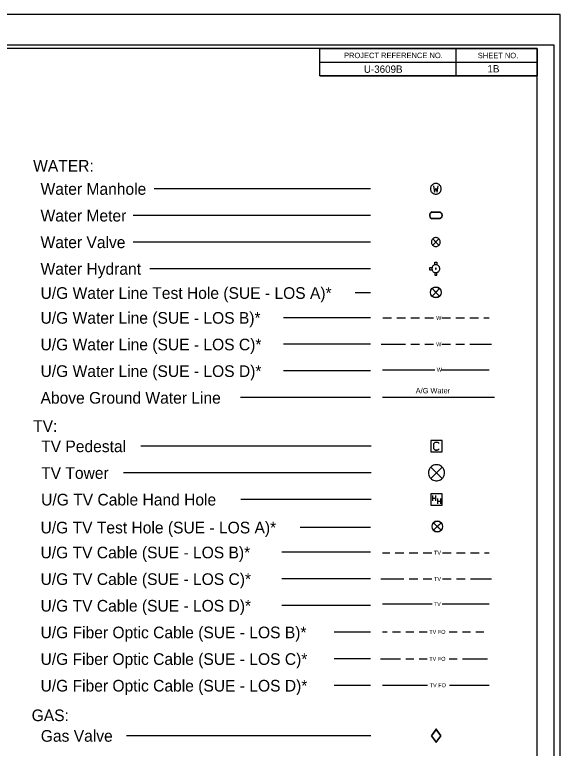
# Model space of a CAD drawing. Extents: x 2594871.4 to 2594905.1, y 784137.6 to 784159.6.
# Drawn here: x 2594897.02 to 2594905.05, y 784148.76 to 784159.56 of the extents above; entities that cross this region are included whole.
import ezdxf

# ---------------------------------------------------------------- set-up
doc = ezdxf.new("R2010")
doc.units = 0
for name, color, linetype in [('Default', 7, 'Continuous'), ('Sheet Data Field CELL', 7, 'Continuous'), ('Sheet Plot Border Inside CELL', 7, 'Continuous'), ('Sheet Plot Border Outside CELL', 7, 'Continuous'), ('Sheet Symbology CELL', 7, 'Continuous')]:
    doc.layers.add(name, color=color, linetype=linetype)

msp = doc.modelspace()

# ---------------------------------------------------------------- linework, layer by layer
at = {"layer": 'Default'}
for p, q in [((2594902.258, 784156.999), (2594899.072, 784156.999)), ((2594902.258, 784156.606), (2594898.765, 784156.606)), ((2594903.159, 784156.657), (2594903.28, 784156.657)), ((2594903.159, 784156.653), (2594903.28, 784156.653)), ((2594903.279, 784156.561), (2594903.159, 784156.561)), ((2594903.279, 784156.557), (2594903.159, 784156.557)), ((2594902.258, 784156.214), (2594898.765, 784156.214)), ((2594902.258, 784155.822), (2594899.006, 784155.822)), ((2594902.258, 784155.467), (2594902.031, 784155.467)), ((2594902.258, 784155.101), (2594900.975, 784155.101)), ((2594902.438, 784155.097), (2594902.565, 784155.097)), ((2594902.644, 784155.097), (2594902.771, 784155.097)), ((2594902.85, 784155.097), (2594902.977, 784155.097)), ((2594903.056, 784155.097), (2594903.183, 784155.097)), ((2594903.309, 784155.097), (2594903.436, 784155.097)), ((2594903.515, 784155.097), (2594903.642, 784155.097)), ((2594903.72, 784155.097), (2594903.848, 784155.097)), ((2594903.926, 784155.097), (2594904.004, 784155.097)), ((2594902.258, 784154.709), (2594900.975, 784154.709)), ((2594902.415, 784154.709), (2594902.771, 784154.709)), ((2594902.85, 784154.709), (2594902.977, 784154.709)), ((2594903.056, 784154.709), (2594903.183, 784154.709)), ((2594903.309, 784154.709), (2594903.436, 784154.709)), ((2594903.515, 784154.709), (2594903.642, 784154.709)), ((2594903.72, 784154.709), (2594904.04, 784154.709)), ((2594902.258, 784154.317), (2594900.975, 784154.317)), ((2594902.434, 784154.334), (2594903.205, 784154.334)), ((2594903.303, 784154.334), (2594904.004, 784154.334)), ((2594902.258, 784153.924), (2594900.341, 784153.924)), ((2594902.434, 784153.929), (2594904.082, 784153.929)), ((2594902.267, 784153.21), (2594898.875, 784153.21)), ((2594903.216, 784153.152), (2594903.241, 784153.152)), ((2594902.267, 784152.817), (2594898.622, 784152.817)), ((2594903.168, 784152.484), (2594903.168, 784152.405)), ((2594903.213, 784152.484), (2594903.213, 784152.405)), ((2594902.267, 784152.425), (2594900.35, 784152.425)), ((2594903.168, 784152.444), (2594903.213, 784152.444)), ((2594903.244, 784152.441), (2594903.244, 784152.362)), ((2594903.244, 784152.401), (2594903.289, 784152.401)), ((2594903.289, 784152.441), (2594903.289, 784152.362)), ((2594902.258, 784152.014), (2594901.221, 784152.014)), ((2594902.258, 784151.647), (2594900.95, 784151.647)), ((2594902.434, 784151.641), (2594902.544, 784151.641)), ((2594902.622, 784151.641), (2594902.75, 784151.641)), ((2594902.828, 784151.641), (2594902.956, 784151.641)), ((2594903.034, 784151.641), (2594903.162, 784151.641)), ((2594903.319, 784151.641), (2594903.446, 784151.641)), ((2594903.525, 784151.641), (2594903.652, 784151.641)), ((2594903.731, 784151.641), (2594903.858, 784151.641)), ((2594903.937, 784151.641), (2594904.004, 784151.641)), ((2594902.258, 784151.255), (2594900.95, 784151.255)), ((2594902.407, 784151.255), (2594902.75, 784151.255)), ((2594902.828, 784151.255), (2594902.956, 784151.255)), ((2594903.034, 784151.255), (2594903.162, 784151.255)), ((2594903.319, 784151.255), (2594903.446, 784151.255)), ((2594903.525, 784151.255), (2594903.652, 784151.255)), ((2594903.731, 784151.255), (2594904.037, 784151.255)), ((2594902.258, 784150.863), (2594900.95, 784150.863)), ((2594902.434, 784150.886), (2594903.164, 784150.886)), ((2594903.311, 784150.886), (2594904.004, 784150.886)), ((2594902.258, 784150.47), (2594901.723, 784150.47)), ((2594902.434, 784150.475), (2594902.503, 784150.475)), ((2594902.582, 784150.475), (2594902.699, 784150.475)), ((2594902.778, 784150.475), (2594902.895, 784150.475)), ((2594902.974, 784150.475), (2594903.092, 784150.475)), ((2594903.415, 784150.475), (2594903.533, 784150.475)), ((2594903.611, 784150.475), (2594903.729, 784150.475)), ((2594903.808, 784150.475), (2594903.925, 784150.475)), ((2594902.258, 784150.078), (2594901.723, 784150.078)), ((2594902.402, 784150.078), (2594902.699, 784150.078)), ((2594902.778, 784150.078), (2594902.895, 784150.078)), ((2594902.974, 784150.078), (2594903.092, 784150.078)), ((2594903.415, 784150.078), (2594903.533, 784150.078)), ((2594903.611, 784150.078), (2594903.979, 784150.078)), ((2594902.258, 784149.686), (2594901.723, 784149.686)), ((2594902.434, 784149.69), (2594903.097, 784149.69)), ((2594903.421, 784149.69), (2594904.004, 784149.69)), ((2594903.223, 784149.039), (2594903.154, 784148.947)), ((2594903.292, 784148.947), (2594903.223, 784149.039)), ((2594902.262, 784148.947), (2594898.663, 784148.947)), ((2594903.154, 784148.947), (2594903.223, 784148.854)), ((2594903.223, 784148.854), (2594903.292, 784148.947))]:
    msp.add_line(p, q, dxfattribs=at)
for points in [[(2594903.219, 784157.078), (2594903.209, 784157.078), (2594903.199, 784157.076), (2594903.19, 784157.073), (2594903.181, 784157.068), (2594903.173, 784157.063), (2594903.165, 784157.057), (2594903.158, 784157.049), (2594903.152, 784157.041), (2594903.147, 784157.033), (2594903.144, 784157.023), (2594903.141, 784157.013), (2594903.14, 784157.004), (2594903.14, 784156.994), (2594903.141, 784156.984), (2594903.144, 784156.974), (2594903.147, 784156.965), (2594903.152, 784156.956), (2594903.158, 784156.948), (2594903.165, 784156.941), (2594903.173, 784156.934), (2594903.181, 784156.929), (2594903.19, 784156.925), (2594903.199, 784156.922), (2594903.21, 784156.92), (2594903.219, 784156.919), (2594903.229, 784156.92), (2594903.239, 784156.922), (2594903.248, 784156.925), (2594903.257, 784156.929), (2594903.266, 784156.934), (2594903.273, 784156.941), (2594903.28, 784156.948), (2594903.286, 784156.956), (2594903.291, 784156.965), (2594903.294, 784156.975), (2594903.297, 784156.984), (2594903.298, 784156.994), (2594903.298, 784157.004), (2594903.297, 784157.013), (2594903.294, 784157.024), (2594903.291, 784157.033), (2594903.286, 784157.041), (2594903.28, 784157.049), (2594903.273, 784157.057), (2594903.266, 784157.063), (2594903.257, 784157.068), (2594903.248, 784157.073), (2594903.239, 784157.076), (2594903.229, 784157.078), (2594903.219, 784157.078)], [(2594903.183, 784157.043), (2594903.2, 784156.95), (2594903.219, 784157.008), (2594903.239, 784156.95), (2594903.255, 784157.043)], [(2594903.159, 784156.657), (2594903.151, 784156.653), (2594903.144, 784156.647), (2594903.138, 784156.64), (2594903.133, 784156.633), (2594903.129, 784156.625), (2594903.127, 784156.616), (2594903.126, 784156.607), (2594903.127, 784156.598), (2594903.129, 784156.589), (2594903.133, 784156.581), (2594903.138, 784156.573), (2594903.144, 784156.567), (2594903.151, 784156.562), (2594903.159, 784156.557)], [(2594903.161, 784156.654), (2594903.153, 784156.649), (2594903.146, 784156.644), (2594903.14, 784156.636), (2594903.135, 784156.629), (2594903.132, 784156.621), (2594903.13, 784156.611), (2594903.13, 784156.603), (2594903.132, 784156.594), (2594903.135, 784156.585), (2594903.14, 784156.577), (2594903.146, 784156.57), (2594903.153, 784156.565), (2594903.161, 784156.561)], [(2594903.277, 784156.654), (2594903.286, 784156.65), (2594903.293, 784156.644), (2594903.299, 784156.637), (2594903.303, 784156.629), (2594903.307, 784156.621), (2594903.308, 784156.611), (2594903.308, 784156.603), (2594903.307, 784156.593), (2594903.303, 784156.585), (2594903.299, 784156.577), (2594903.292, 784156.57), (2594903.285, 784156.565), (2594903.277, 784156.56)], [(2594903.279, 784156.657), (2594903.287, 784156.653), (2594903.294, 784156.647), (2594903.3, 784156.64), (2594903.305, 784156.633), (2594903.309, 784156.625), (2594903.311, 784156.616), (2594903.312, 784156.607), (2594903.311, 784156.598), (2594903.309, 784156.589), (2594903.305, 784156.581), (2594903.3, 784156.573), (2594903.294, 784156.567), (2594903.287, 784156.562), (2594903.279, 784156.557)], [(2594903.284, 784156.214), (2594903.283, 784156.224), (2594903.281, 784156.234), (2594903.278, 784156.242), (2594903.273, 784156.251), (2594903.267, 784156.258), (2594903.26, 784156.265), (2594903.252, 784156.271), (2594903.243, 784156.275), (2594903.234, 784156.278), (2594903.224, 784156.279), (2594903.214, 784156.279), (2594903.205, 784156.278), (2594903.195, 784156.275), (2594903.186, 784156.271), (2594903.179, 784156.265), (2594903.171, 784156.258), (2594903.166, 784156.251), (2594903.16, 784156.242), (2594903.157, 784156.234), (2594903.155, 784156.224), (2594903.154, 784156.214), (2594903.155, 784156.205), (2594903.157, 784156.195), (2594903.16, 784156.186), (2594903.166, 784156.177), (2594903.171, 784156.17), (2594903.179, 784156.163), (2594903.186, 784156.158), (2594903.195, 784156.153), (2594903.205, 784156.15), (2594903.214, 784156.149), (2594903.224, 784156.149), (2594903.234, 784156.15), (2594903.243, 784156.153), (2594903.252, 784156.158), (2594903.26, 784156.163), (2594903.267, 784156.17), (2594903.273, 784156.177), (2594903.278, 784156.186), (2594903.281, 784156.195), (2594903.283, 784156.205), (2594903.284, 784156.214)], [(2594903.265, 784156.168), (2594903.173, 784156.26), (2594903.219, 784156.214), (2594903.173, 784156.168), (2594903.265, 784156.26)], [(2594903.163, 784155.837), (2594903.126, 784155.837), (2594903.126, 784155.807), (2594903.163, 784155.807)], [(2594903.218, 784155.88), (2594903.209, 784155.879), (2594903.2, 784155.877), (2594903.191, 784155.873), (2594903.184, 784155.868), (2594903.177, 784155.862), (2594903.171, 784155.854), (2594903.166, 784155.846), (2594903.163, 784155.837), (2594903.161, 784155.828), (2594903.161, 784155.819), (2594903.163, 784155.81), (2594903.165, 784155.801), (2594903.169, 784155.793), (2594903.175, 784155.785), (2594903.181, 784155.778), (2594903.189, 784155.772), (2594903.197, 784155.768), (2594903.206, 784155.765), (2594903.215, 784155.764), (2594903.224, 784155.764), (2594903.233, 784155.765), (2594903.242, 784155.769), (2594903.251, 784155.773), (2594903.258, 784155.779), (2594903.264, 784155.786), (2594903.27, 784155.793), (2594903.273, 784155.802), (2594903.276, 784155.811), (2594903.277, 784155.82), (2594903.276, 784155.829), (2594903.275, 784155.838), (2594903.271, 784155.847), (2594903.267, 784155.856), (2594903.26, 784155.863), (2594903.253, 784155.869), (2594903.245, 784155.874), (2594903.236, 784155.877), (2594903.227, 784155.879), (2594903.218, 784155.88)], [(2594903.205, 784155.878), (2594903.205, 784155.916), (2594903.235, 784155.916), (2594903.235, 784155.878)], [(2594903.219, 784155.829), (2594903.216, 784155.828), (2594903.214, 784155.826), (2594903.212, 784155.823), (2594903.213, 784155.82), (2594903.215, 784155.817), (2594903.218, 784155.815), (2594903.221, 784155.815), (2594903.224, 784155.817), (2594903.225, 784155.82), (2594903.226, 784155.823), (2594903.224, 784155.826), (2594903.222, 784155.828), (2594903.219, 784155.829)], [(2594903.205, 784155.765), (2594903.205, 784155.728), (2594903.235, 784155.728), (2594903.235, 784155.766)], [(2594903.274, 784155.529), (2594903.163, 784155.419), (2594903.218, 784155.474), (2594903.163, 784155.529), (2594903.274, 784155.419)], [(2594903.163, 784155.529), (2594903.218, 784155.474), (2594903.274, 784155.529)], [(2594903.274, 784155.419), (2594903.218, 784155.474), (2594903.163, 784155.419)], [(2594903.147, 784153.128), (2594903.31, 784153.128), (2594903.31, 784153.291), (2594903.147, 784153.291), (2594903.147, 784153.128)], [(2594903.267, 784153.17), (2594903.247, 784153.152), (2594903.21, 784153.152), (2594903.191, 784153.17), (2594903.191, 784153.249), (2594903.21, 784153.267), (2594903.247, 784153.267), (2594903.267, 784153.249)], [(2594903.347, 784152.817), (2594903.345, 784152.834), (2594903.341, 784152.853), (2594903.335, 784152.868), (2594903.326, 784152.884), (2594903.315, 784152.897), (2594903.302, 784152.909), (2594903.288, 784152.92), (2594903.272, 784152.928), (2594903.255, 784152.933), (2594903.238, 784152.935), (2594903.219, 784152.935), (2594903.202, 784152.933), (2594903.185, 784152.928), (2594903.169, 784152.92), (2594903.155, 784152.909), (2594903.142, 784152.897), (2594903.131, 784152.884), (2594903.122, 784152.868), (2594903.116, 784152.853), (2594903.112, 784152.834), (2594903.11, 784152.817), (2594903.112, 784152.8), (2594903.116, 784152.782), (2594903.122, 784152.766), (2594903.131, 784152.75), (2594903.142, 784152.737), (2594903.155, 784152.725), (2594903.169, 784152.715), (2594903.185, 784152.707), (2594903.202, 784152.702), (2594903.219, 784152.699), (2594903.238, 784152.699), (2594903.255, 784152.702), (2594903.272, 784152.707), (2594903.288, 784152.715), (2594903.302, 784152.725), (2594903.315, 784152.737), (2594903.326, 784152.75), (2594903.335, 784152.766), (2594903.341, 784152.782), (2594903.345, 784152.8), (2594903.347, 784152.817)], [(2594903.312, 784152.733), (2594903.144, 784152.901), (2594903.228, 784152.817), (2594903.144, 784152.733), (2594903.312, 784152.901)], [(2594903.144, 784152.34), (2594903.313, 784152.34), (2594903.313, 784152.509), (2594903.144, 784152.509), (2594903.144, 784152.34)], [(2594903.296, 784152.082), (2594903.185, 784151.971), (2594903.241, 784152.027), (2594903.185, 784152.082), (2594903.296, 784151.971)], [(2594903.185, 784152.082), (2594903.241, 784152.027), (2594903.296, 784152.082)], [(2594903.296, 784151.971), (2594903.241, 784152.027), (2594903.185, 784151.971)], [(2594903.223, 784149.047), (2594903.148, 784148.947), (2594903.223, 784148.846), (2594903.298, 784148.947), (2594903.223, 784149.047)]]:
    msp.add_lwpolyline(points, dxfattribs=at)
for centre in [(2594903.218, 784155.474), (2594903.241, 784152.027)]:
    msp.add_circle(centre, 0.0784, dxfattribs=at)
for centre, start, end in [((2594903.218, 784155.474), 45, 135), ((2594903.218, 784155.474), 225, 315), ((2594903.241, 784152.027), 45, 135), ((2594903.241, 784152.027), 225, 315)]:
    msp.add_arc(centre, 0.0784, start, end, dxfattribs=at)
at = {"layer": 'Sheet Plot Border Inside CELL'}
msp.add_lwpolyline([(2594871.632, 784138.011), (2594904.962, 784138.011), (2594904.962, 784159.113), (2594871.632, 784159.113)], close=True, dxfattribs=at)
at = {"layer": 'Sheet Plot Border Outside CELL'}
msp.add_lwpolyline([(2594905.052, 784159.562), (2594871.372, 784159.562), (2594871.372, 784137.562), (2594905.052, 784137.562)], close=True, dxfattribs=at)
at = {"layer": 'Sheet Symbology CELL'}
for p, q in [((2594903.512, 784159.061), (2594903.512, 784158.661)), ((2594901.511, 784158.861), (2594904.712, 784158.861)), ((2594901.511, 784158.661), (2594904.712, 784158.661))]:
    msp.add_line(p, q, dxfattribs=at)
for points in [[(2594904.712, 784159.062), (2594874.712, 784159.062), (2594874.712, 784138.082), (2594904.712, 784138.082)], [(2594901.511, 784159.062), (2594904.712, 784159.062), (2594904.712, 784158.661), (2594901.511, 784158.661)]]:
    msp.add_lwpolyline(points, close=True, dxfattribs=at)

# ---------------------------------------------------------------- texts
at = {"layer": 'Default'}
for s, height, p in [('WATER:', 0.1716, (2594897.29, 784157.251)), ('Water Manhole', 0.17164, (2594897.399, 784156.91)), ('Water Meter', 0.17164, (2594897.399, 784156.517)), ('Water Valve', 0.17164, (2594897.399, 784156.125)), ('Water Hydrant', 0.17164, (2594897.399, 784155.733)), ('U/G Water Line Test Hole (SUE - LOS A)*', 0.17164, (2594897.399, 784155.378)), ('U/G Water Line (SUE - LOS B)*', 0.17164, (2594897.399, 784155.012)), ('W', 0.0588, (2594903.224, 784155.068)), ('U/G Water Line (SUE - LOS C)*', 0.17164, (2594897.399, 784154.62)), ('W', 0.0588, (2594903.224, 784154.68)), ('U/G Water Line (SUE - LOS D)*', 0.17164, (2594897.399, 784154.228)), ('W', 0.0588, (2594903.233, 784154.305)), ('Above Ground Water Line', 0.17164, (2594897.399, 784153.835)), ('A/G Water', 0.0785, (2594902.923, 784153.987)), ('TV:', 0.1716, (2594897.29, 784153.42)), ('TV Pedestal', 0.17164, (2594897.408, 784153.121)), ('TV Tower', 0.1716, (2594897.408, 784152.728)), ('U/G TV Cable Hand Hole', 0.17164, (2594897.408, 784152.336)), ('U/G TV Test Hole (SUE - LOS A)*', 0.17164, (2594897.399, 784151.925)), ('U/G TV Cable (SUE - LOS B)*', 0.17164, (2594897.399, 784151.558)), ('TV', 0.0588, (2594903.192, 784151.611)), ('U/G TV Cable (SUE - LOS C)*', 0.17164, (2594897.399, 784151.166)), ('TV', 0.0588, (2594903.192, 784151.225)), ('U/G TV Cable (SUE - LOS D)*', 0.17164, (2594897.399, 784150.774)), ('TV', 0.0588, (2594903.189, 784150.857)), ('U/G Fiber Optic Cable (SUE - LOS B)*', 0.17164, (2594897.399, 784150.381)), ('TV FO', 0.0588, (2594903.122, 784150.446)), ('U/G Fiber Optic Cable (SUE - LOS C)*', 0.17164, (2594897.399, 784149.989)), ('TV FO', 0.0588, (2594903.122, 784150.049)), ('U/G Fiber Optic Cable (SUE - LOS D)*', 0.17164, (2594897.399, 784149.597)), ('TV FO', 0.0588, (2594903.128, 784149.661)), ('GAS:', 0.1716, (2594897.268, 784149.161)), ('Gas Valve', 0.1716, (2594897.403, 784148.858))]:
    msp.add_text(s, height=height, rotation=360, dxfattribs=at).set_placement(p)
at = {"layer": 'Sheet Data Field CELL'}
for s, p in [('U-3609B', (2594902.159, 784158.706)), ('1B ', (2594903.979, 784158.711))]:
    msp.add_text(s, height=0.108, rotation=360, dxfattribs=at).set_placement(p)
at = {"layer": 'Sheet Symbology CELL'}
for s, p in [('PROJECT REFERENCE NO.', (2594901.867, 784158.922)), ('SHEET NO.', (2594903.837, 784158.921))]:
    msp.add_text(s, height=0.08, rotation=360, dxfattribs=at).set_placement(p)

doc.saveas('drawing.dxf')
